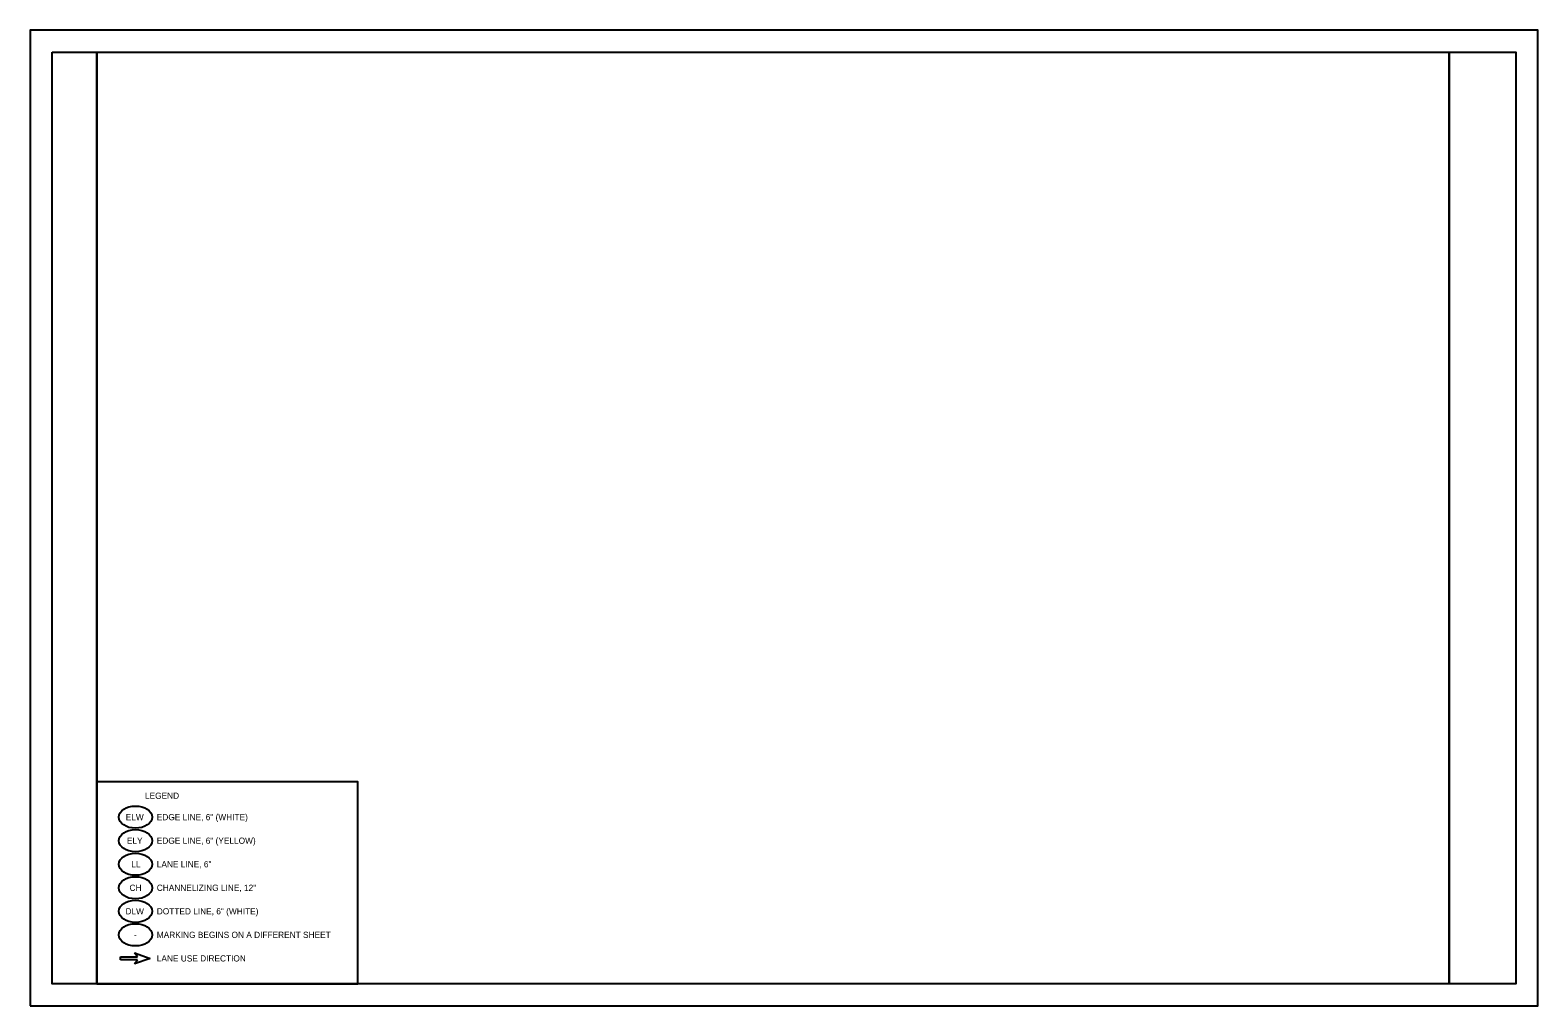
# Model space of a CAD drawing. Extents: x 0 to 34, y 0 to 22.
import ezdxf

# ---------------------------------------------------------------- set-up
doc = ezdxf.new("R2010")
doc.units = 0
for name, color, linetype in [('DR_X_Elev_Flow', 7, 'Continuous'), ('SG_X_Manhole', 7, 'Continuous'), ('SV_X_Shot_Marker', 7, 'Continuous')]:
    doc.layers.add(name, color=color, linetype=linetype)

msp = doc.modelspace()

# ---------------------------------------------------------------- linework, layer by layer
at = {"layer": 'DR_X_Elev_Flow'}
msp.add_line((32, 0.5), (32, 21.5), dxfattribs=at)
for points in [[(0, 0), (34, 0), (34, 22), (0, 22)], [(0.5, 21.5), (1.5, 21.5), (1.5, 0.5), (0.5, 0.5)], [(1.5, 21.5), (33.5, 21.5), (33.5, 0.5), (1.5, 0.5)]]:
    msp.add_lwpolyline(points, close=True, dxfattribs=at)
at = {"layer": 'SG_X_Manhole'}
msp.add_lwpolyline([(1.5, 0.5), (7.386, 0.5), (7.386, 5.052), (1.5, 5.052)], close=True, dxfattribs=at)
at = {"layer": 'SV_X_Shot_Marker'}
for p, q in [((2.038, 1.035), (2.038, 1.105)), ((2.038, 1.105), (2.423, 1.105)), ((2.038, 1.07), (2.038, 1.07)), ((2.423, 1.035), (2.038, 1.035)), ((2.423, 1.105), (2.353, 1.192)), ((2.353, 1.192), (2.703, 1.07)), ((2.703, 1.07), (2.353, 0.948)), ((2.353, 0.948), (2.423, 1.035)), ((2.703, 1.07), (2.703, 1.07))]:
    msp.add_line(p, q, dxfattribs=at)
msp.add_lwpolyline([(1.5, 21.5), (32, 21.5), (32, 0.5), (1.5, 0.5)], close=True, dxfattribs=at)
for centre in [(2.375, 4.255), (2.375, 3.724), (2.375, 3.193), (2.375, 2.662), (2.375, 2.132), (2.375, 1.601)]:
    msp.add_ellipse(centre, major_axis=(0.375, 0), ratio=0.666667, dxfattribs=at)

# ---------------------------------------------------------------- texts
for s, p in [('LEGEND', (2.589, 4.668)), ('ELW', (2.155, 4.185)), ('EDGE LINE, 6" (WHITE)', (2.856, 4.185)), ('ELY', (2.181, 3.654)), ('EDGE LINE, 6" (YELLOW) ', (2.856, 3.654)), ('LL', (2.28, 3.123)), ('LANE LINE, 6"', (2.856, 3.123)), ('CH', (2.241, 2.592)), ('CHANNELIZING LINE, 12"', (2.856, 2.592)), ('DLW', (2.15, 2.062)), ('DOTTED LINE, 6" (WHITE) ', (2.856, 2.062)), ('-', (2.344, 1.531)), ('MARKING BEGINS ON A DIFFERENT SHEET', (2.856, 1.531)), ('LANE USE DIRECTION', (2.856, 1))]:
    msp.add_text(s, height=0.14, dxfattribs=at).set_placement(p)

doc.saveas('drawing.dxf')
